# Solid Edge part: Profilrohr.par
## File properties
Username: bmolnar
Dokumentum tartalom típus: 0
Author: bmolnar
Last saved by: bmolnar
Revision: 80
Sűrűség: 0,000 kg/m^3
Pontosság: 0,990
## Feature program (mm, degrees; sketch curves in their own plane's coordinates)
base feature "unnamed BaseFeature 1"
thread "unnamed Thread 1"
thread "Menet_2"  ThreadDepth = 5.5 mm
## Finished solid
Body 1: solid body, 127 faces, 307 edges, 198 vertices.
  Faces by surface: cylinder 57, plane 52, cone 16, torus 2
  Edges by curve: line 144, circle 142, spline 9, curve on surface 7, intersection 5
Bounding box of the edges (mm; curved faces can reach further): 30.000 x 34.000 x 52.000, from (-15, -15, 0) to (15, 19, 52).
Cylindrical faces by radius (mm): R0.3 x24, R0.65 x2, R1.85 x4, R2 x2, R2.067 x4, R2.35 x2, R2.8 x4, R3.75 x4, R8 x1, R8.95 x2, R9.1 x2, R9.5 x2, R20 x4
Conical faces (half-angle, radius in mm at the cone's reference point): 45 deg R2.317 x2, 45 deg R2.95 x4, 45 deg R3.9 x4, 45 deg R8.4 x2, 45 deg R9.2 x2, 45 deg R9.25 x2
Toroidal faces (ring radius, tube radius in mm): R9.4 r0.1 x2
Planar faces by outward normal: +x 6, +y 9, +z 9, -x 6, -y 5, -z 9, oblique 8
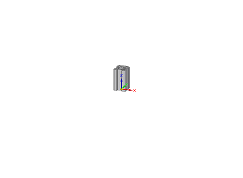
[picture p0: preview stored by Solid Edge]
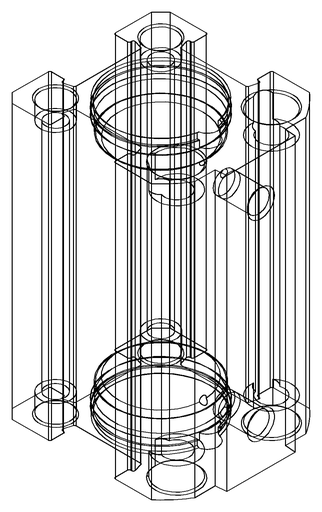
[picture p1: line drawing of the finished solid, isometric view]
